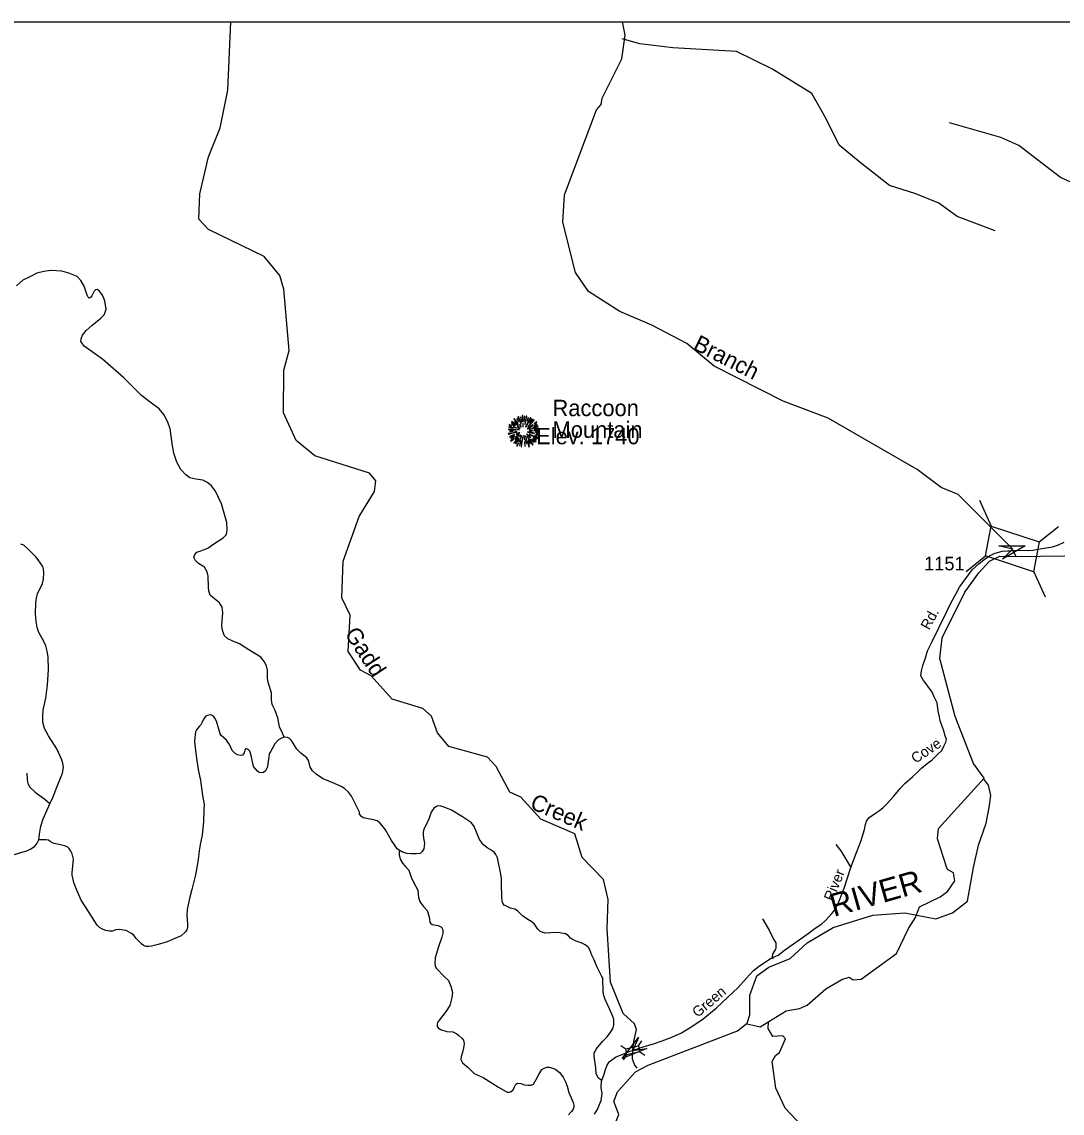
# Model space of a CAD drawing. Extents: x 990631 to 1056237, y 535999 to 585651.
# Drawn here: x 1012421 to 1021960, y 575643 to 585651 of the extents above; entities that cross this region are included whole.
import ezdxf

# ---------------------------------------------------------------- set-up
doc = ezdxf.new("R2010")
doc.units = 0
for name, color, linetype in [('Exist Geographical Mountain Summit CELL', 7, 'Continuous'), ('Exist Geographical Mountain Summit Elevation Number Label', 7, 'Continuous'), ('Exist Geographical Mountain Summit Label', 7, 'Continuous'), ('Exist Hydrographic Creek Single Shore', 7, 'Continuous'), ('Exist Hydrographic Creek Single Shore Label', 7, 'Continuous'), ('Exist Hydrographic River Shore', 7, 'Continuous'), ('Exist Hydrographic River Shore Label', 7, 'Continuous'), ('Exist Road Non-System Type 51', 7, 'Continuous'), ('Exist Road Secondary Structure Standard Bridge Attributed CELL', 7, 'Continuous'), ('Exist Road Secondary Structure Standard Bridge CELL', 7, 'Continuous'), ('Exist Road Secondary Type 51 Attributed', 7, 'Continuous'), ('Exist Road Secondary Type 51 Label', 7, 'Continuous'), ('Exist Road Secondary Type 51 Number Label', 7, 'Continuous'), ('Scratch_Level_3', 7, 'Continuous')]:
    doc.layers.add(name, color=color, linetype=linetype)

msp = doc.modelspace()

# ---------------------------------------------------------------- linework, layer by layer
at = {"layer": 'Exist Geographical Mountain Summit CELL'}
for points in [[(1016911, 581982), (1016951, 581952), (1016953, 581954), (1016915, 581987)], [(1016931, 582007), (1016967, 581970), (1016971, 581972), (1016935, 582012)], [(1016939, 581980), (1016972, 581951), (1016974, 581953), (1016942, 581985)], [(1016959, 582009), (1016975, 581987), (1016976, 581988), (1016963, 582013)], [(1016970, 582030), (1016996, 581964), (1016999, 581965), (1016975, 582033)], [(1017004, 581979), (1017006, 581979), (1016997, 582027), (1016993, 582026)], [(1017008, 582040), (1017013, 581988), (1017016, 581988), (1017014, 582041)], [(1017024, 581986), (1017028, 581986), (1017032, 582033), (1017027, 582033)], [(1017036, 581957), (1017051, 582034), (1017046, 582036), (1017033, 581958)], [(1017040, 581936), (1017043, 581934), (1017091, 582018), (1017086, 582022)], [(1017054, 581993), (1017058, 581992), (1017067, 582018), (1017062, 582020)], [(1017061, 581937), (1017063, 581935), (1017119, 581999), (1017115, 582004)], [(1017098, 582009), (1017077, 581975), (1017080, 581974), (1017103, 582005)], [(1017119, 581965), (1017120, 581963), (1017143, 581979), (1017140, 581982)], [(1016881, 581875), (1016883, 581869), (1016919, 581880), (1016917, 581883)], [(1016883, 581912), (1016955, 581905), (1016955, 581908), (1016883, 581917)], [(1016885, 581933), (1016927, 581924), (1016928, 581927), (1016886, 581938)], [(1016888, 581953), (1016911, 581944), (1016912, 581947), (1016890, 581958)], [(1016895, 581895), (1016924, 581896), (1016924, 581900), (1016894, 581900)], [(1016910, 581964), (1016936, 581947), (1016938, 581950), (1016913, 581968)], [(1016927, 581936), (1016957, 581924), (1016958, 581926), (1016929, 581940)], [(1016927, 581886), (1016928, 581881), (1016961, 581889), (1016961, 581893)], [(1016955, 581872), (1016957, 581867), (1016986, 581882), (1016985, 581885)], [(1016963, 581941), (1016988, 581922), (1016990, 581925), (1016966, 581944)], [(1016963, 581911), (1016980, 581909), (1016981, 581911), (1016964, 581916)], [(1016983, 581954), (1016996, 581938), (1016999, 581940), (1016986, 581957)], [(1017014, 581967), (1017015, 581937), (1017018, 581938), (1017018, 581967)], [(1017058, 581917), (1017059, 581915), (1017108, 581951), (1017105, 581955)], [(1017059, 581888), (1017120, 581876), (1017121, 581880), (1017060, 581891)], [(1017074, 581901), (1017074, 581899), (1017104, 581899), (1017104, 581904)], [(1017075, 581914), (1017076, 581912), (1017154, 581941), (1017152, 581945)], [(1017119, 581942), (1017146, 581957), (1017143, 581962), (1017117, 581945)], [(1017117, 581900), (1017169, 581904), (1017169, 581908), (1017117, 581904)], [(1017120, 581914), (1017157, 581921), (1017156, 581926), (1017119, 581916)], [(1017132, 581888), (1017158, 581886), (1017158, 581891), (1017132, 581892)], [(1016891, 581847), (1016894, 581842), (1016939, 581862), (1016938, 581867)], [(1016902, 581810), (1016905, 581806), (1016934, 581827), (1016931, 581831)], [(1016909, 581831), (1016938, 581848), (1016935, 581851), (1016906, 581836)], [(1016933, 581791), (1016936, 581788), (1016977, 581836), (1016974, 581838)], [(1016949, 581822), (1016968, 581840), (1016964, 581842), (1016944, 581825)], [(1016945, 581840), (1016948, 581837), (1016982, 581865), (1016980, 581868)], [(1016973, 581822), (1016948, 581783), (1016951, 581780), (1016977, 581820)], [(1016958, 581763), (1016963, 581760), (1016974, 581785), (1016971, 581787)], [(1016976, 581800), (1016981, 581799), (1017007, 581857), (1017005, 581858)], [(1016983, 581850), (1016987, 581847), (1016997, 581863), (1016995, 581865)], [(1016988, 581765), (1017000, 581808), (1016996, 581808), (1016984, 581766)], [(1016998, 581755), (1017003, 581754), (1017015, 581843), (1017012, 581844)], [(1017023, 581859), (1017027, 581822), (1017032, 581822), (1017027, 581860)], [(1017030, 581800), (1017033, 581758), (1017037, 581759), (1017034, 581800)], [(1017039, 581850), (1017048, 581820), (1017052, 581822), (1017041, 581851)], [(1017049, 581784), (1017044, 581814), (1017040, 581814), (1017045, 581783)], [(1017048, 581871), (1017086, 581835), (1017089, 581840), (1017050, 581873)], [(1017054, 581848), (1017104, 581773), (1017108, 581776), (1017056, 581849)], [(1017054, 581805), (1017071, 581755), (1017076, 581757), (1017057, 581806)], [(1017064, 581811), (1017080, 581782), (1017084, 581784), (1017068, 581812)], [(1017073, 581868), (1017151, 581830), (1017153, 581835), (1017074, 581871)], [(1017086, 581822), (1017116, 581793), (1017120, 581796), (1017088, 581825)], [(1017103, 581823), (1017133, 581797), (1017137, 581801), (1017105, 581826)], [(1017112, 581834), (1017137, 581821), (1017140, 581824), (1017114, 581838)], [(1017126, 581858), (1017147, 581850), (1017149, 581854), (1017128, 581861)], [(1017136, 581871), (1017164, 581864), (1017165, 581869), (1017137, 581876)]]:
    msp.add_lwpolyline(points, close=True, dxfattribs=at)
at = {"layer": 'Exist Hydrographic Creek Single Shore'}
for points in [[(1018062, 576055), (1018038, 576089), (1018020, 576137), (1018024, 576222), (1018031, 576299), (1018056, 576411), (1018038, 576463), (1017936, 576557), (1017818, 576845), (1017789, 577337), (1017798, 577603), (1017754, 577787), (1017560, 577988), (1017493, 578206), (1017180, 578340), (1016995, 578541), (1016897, 578586), (1016771, 578821), (1016691, 578908), (1016335, 579004), (1016231, 579131), (1016178, 579283), (1016097, 579353), (1015816, 579438), (1015623, 579652), (1015525, 579706), (1015414, 579876), (1015433, 580210), (1015355, 580369), (1015366, 580704), (1015513, 581114), (1015655, 581345), (1015666, 581443), (1015610, 581513), (1015107, 581671), (1014936, 581812), (1014820, 582064), (1014824, 582458), (1014872, 582637), (1014824, 583199), (1014787, 583325), (1014642, 583498), (1014134, 583748), (1014045, 583842), (1014053, 584075), (1014131, 584414), (1014240, 584678), (1014310, 585025), (1014338, 585651)], [(1021538, 580749), (1021499, 580823), (1021007, 581316), (1020851, 581381), (1020631, 581546), (1019813, 582016), (1019401, 582172), (1018770, 582493), (1018518, 582701), (1018199, 582869), (1017903, 582996), (1017617, 583179), (1017498, 583352), (1017380, 583814), (1017396, 584063), (1017689, 584845), (1017733, 584893), (1017743, 584952), (1017922, 585313), (1017954, 585529), (1017930, 585651)], [(1021345, 583733), (1020996, 583867), (1020829, 583988), (1020617, 584075), (1020376, 584150), (1020109, 584362), (1019914, 584521), (1019797, 584762), (1019664, 584995), (1019298, 585220), (1018973, 585378), (1018390, 585412), (1018086, 585449), (1017924, 585495)], [(1022224, 584098), (1021945, 584222), (1021563, 584518), (1021399, 584590), (1020928, 584725)], [(1019069, 576461), (1019152, 576444), (1019191, 576434), (1019430, 576580), (1019550, 576604), (1019623, 576633), (1019792, 576783), (1019941, 576869), (1020007, 576889), (1020044, 576866), (1020117, 576872), (1020441, 577107), (1020550, 577336), (1020614, 577438), (1020653, 577535), (1020842, 577628), (1020909, 577677), (1020975, 577774), (1020965, 577847), (1020909, 577877), (1020899, 577902), (1020816, 578158), (1020825, 578254), (1020972, 578416), (1021244, 578714)], [(1023226, 574096), (1023161, 574140), (1023081, 574234), (1022486, 574403), (1022213, 574731), (1021668, 574889), (1021391, 575065), (1021135, 575166), (1020820, 575218), (1020196, 575241), (1019826, 575419), (1019573, 575526), (1019420, 575689), (1019334, 575871), (1019301, 576117), (1019331, 576173), (1019367, 576200), (1019424, 576326), (1019400, 576353), (1019307, 576346), (1019264, 576419), (1019268, 576481)]]:
    msp.add_lwpolyline(points, dxfattribs=at)
at = {"layer": 'Exist Hydrographic River Shore'}
for points in [[(1021244, 578714), (1021147, 578851), (1020978, 579281), (1020837, 579812), (1020860, 580002), (1021066, 580422), (1021197, 580599), (1021293, 580705), (1021388, 580752), (1021538, 580749)], [(1021538, 580749), (1021984, 580755)], [(1019161, 576902), (1019271, 576982), (1019467, 577062), (1019623, 577204), (1019861, 577347), (1020225, 577459), (1020517, 577479), (1020802, 577426), (1020955, 577479), (1021091, 577586), (1021147, 577897), (1021194, 578100), (1021263, 578303), (1021290, 578446), (1021307, 578556), (1021283, 578652), (1021240, 578712)], [(1019072, 576468), (1019095, 576544), (1019095, 576726), (1019161, 576902)], [(1018164, 576082), (1018982, 576398), (1019072, 576468)], [(1017640, 575384), (1017849, 575518), (1017896, 575631), (1017849, 575751), (1017884, 575838), (1018048, 576021), (1018164, 576082)]]:
    msp.add_lwpolyline(points, dxfattribs=at)
at = {"layer": 'Exist Road Non-System Type 51'}
for points in [[(1014827, 579090), (1014810, 579128), (1014784, 579185), (1014767, 579268), (1014743, 579337), (1014717, 579392), (1014710, 579432), (1014711, 579498), (1014687, 579575), (1014678, 579607), (1014675, 579637), (1014673, 579705), (1014665, 579746), (1014642, 579786), (1014611, 579824), (1014502, 579893), (1014417, 579948), (1014348, 579974), (1014309, 579992), (1014280, 580021), (1014263, 580059), (1014255, 580106), (1014259, 580164), (1014261, 580189), (1014263, 580235), (1014257, 580284), (1014234, 580322), (1014171, 580371), (1014148, 580393), (1014137, 580434), (1014132, 580468), (1014130, 580566), (1014121, 580608), (1014097, 580651), (1014042, 580685), (1014009, 580714), (1013997, 580739), (1014006, 580766), (1014025, 580788), (1014063, 580800), (1014126, 580824), (1014182, 580863), (1014268, 580920), (1014294, 580947), (1014301, 580967), (1014304, 580998), (1014300, 581061), (1014252, 581230), (1014198, 581348), (1014159, 581396), (1014117, 581429), (1014081, 581448), (1014017, 581456), (1013960, 581470), (1013925, 581496), (1013878, 581547), (1013841, 581612), (1013815, 581695), (1013803, 581762), (1013781, 581919), (1013761, 581979), (1013723, 582049), (1013679, 582102), (1013599, 582163), (1013517, 582224), (1013356, 582387), (1013160, 582556), (1012991, 582676), (1012970, 582706), (1012963, 582721), (1012966, 582744), (1012977, 582778), (1013012, 582821), (1013062, 582867), (1013144, 582935), (1013177, 582965), (1013186, 582987), (1013195, 583017), (1013183, 583091), (1013161, 583144), (1013130, 583185), (1013113, 583196), (1013097, 583192), (1013084, 583181), (1013063, 583137), (1013050, 583122), (1013038, 583118), (1013028, 583125), (1013019, 583143), (1012992, 583228), (1012963, 583279), (1012927, 583316), (1012852, 583347), (1012788, 583365), (1012688, 583370), (1012622, 583362), (1012559, 583346), (1012494, 583313), (1012431, 583281), (1012371, 583229)], [(1012679, 578483), (1012701, 578528), (1012742, 578631), (1012795, 578761), (1012803, 578813), (1012796, 578853), (1012785, 578888), (1012742, 578983), (1012666, 579102), (1012630, 579171), (1012614, 579228), (1012615, 579252), (1012614, 579280), (1012618, 579338), (1012642, 579449), (1012656, 579571), (1012664, 579710), (1012662, 579829), (1012654, 579881), (1012640, 579929), (1012617, 579980), (1012578, 580050), (1012563, 580098), (1012551, 580151), (1012545, 580225), (1012549, 580321), (1012554, 580367), (1012566, 580410), (1012585, 580448), (1012609, 580499), (1012620, 580540), (1012624, 580600), (1012621, 580632), (1012612, 580655), (1012572, 580716), (1012549, 580745), (1012481, 580813), (1012438, 580851), (1012412, 580860)], [(1014827, 579090), (1014801, 579083), (1014774, 579068), (1014741, 579029), (1014703, 578964), (1014690, 578938), (1014685, 578908), (1014677, 578849), (1014672, 578819), (1014665, 578801), (1014655, 578783), (1014638, 578768), (1014616, 578765), (1014598, 578767), (1014581, 578778), (1014544, 578821), (1014523, 578924), (1014513, 578962), (1014497, 578979), (1014485, 578985), (1014471, 578984), (1014467, 578972), (1014460, 578948), (1014445, 578926), (1014427, 578923), (1014397, 578930), (1014378, 578941), (1014351, 578970), (1014324, 579024), (1014298, 579063), (1014249, 579105), (1014240, 579123), (1014207, 579237), (1014192, 579265), (1014177, 579284), (1014161, 579292), (1014147, 579295), (1014123, 579291), (1014109, 579284), (1014086, 579255), (1014073, 579229), (1014062, 579205), (1014048, 579188), (1014021, 579159), (1014014, 579141), (1014009, 579113), (1014006, 579087), (1014003, 579047), (1014019, 578919), (1014039, 578796), (1014059, 578695), (1014079, 578556), (1014092, 578474), (1014091, 578428), (1014087, 578318), (1014075, 578192), (1014058, 578123), (1014049, 578069), (1014034, 577947), (1014012, 577830), (1013980, 577695), (1013959, 577612), (1013948, 577568), (1013938, 577512), (1013934, 577456), (1013939, 577380), (1013940, 577346), (1013933, 577324), (1013923, 577307), (1013882, 577270), (1013825, 577244), (1013752, 577214), (1013671, 577189), (1013610, 577173), (1013584, 577170), (1013562, 577171), (1013536, 577179), (1013519, 577196), (1013469, 577244), (1013444, 577279), (1013420, 577293), (1013379, 577319), (1013353, 577322), (1013317, 577327), (1013283, 577324), (1013249, 577313), (1013225, 577312), (1013187, 577317), (1013155, 577332), (1013134, 577347), (1013112, 577366), (1013033, 577491), (1012966, 577597), (1012916, 577709), (1012899, 577757), (1012882, 577824), (1012882, 577848), (1012894, 577971), (1012882, 578020), (1012869, 578046)], [(1015881, 578054), (1015862, 578067), (1015837, 578103), (1015812, 578142), (1015755, 578240), (1015723, 578285), (1015702, 578306), (1015678, 578323), (1015648, 578334), (1015595, 578342), (1015551, 578351), (1015535, 578362), (1015518, 578386), (1015516, 578402), (1015479, 578478), (1015443, 578549), (1015417, 578586), (1015378, 578619), (1015350, 578638), (1015289, 578666), (1015183, 578708), (1015122, 578748), (1015087, 578783), (1015064, 578816), (1015052, 578870), (1015035, 578901), (1014978, 578945), (1014942, 578980), (1014909, 579035), (1014892, 579062), (1014875, 579080), (1014857, 579087), (1014827, 579090)], [(1012467, 578762), (1012469, 578706), (1012472, 578676), (1012479, 578662), (1012492, 578635), (1012543, 578586), (1012631, 578521), (1012679, 578483)], [(1012576, 578150), (1012584, 578200), (1012596, 578274), (1012617, 578341), (1012643, 578402), (1012675, 578473), (1012679, 578483)], [(1017738, 575942), (1017717, 575957), (1017709, 575965), (1017694, 575990), (1017688, 576004), (1017684, 576060), (1017669, 576165), (1017670, 576195), (1017677, 576209), (1017688, 576230), (1017746, 576299), (1017788, 576343), (1017821, 576388), (1017840, 576419), (1017849, 576449), (1017850, 576477), (1017849, 576501), (1017840, 576528), (1017810, 576599), (1017769, 576686), (1017756, 576722), (1017751, 576755), (1017749, 576881), (1017740, 576897), (1017693, 576989), (1017669, 577048), (1017646, 577092), (1017630, 577141), (1017617, 577161), (1017585, 577186), (1017550, 577204), (1017504, 577219), (1017469, 577236), (1017451, 577249), (1017430, 577272), (1017407, 577286), (1017369, 577294), (1017343, 577301), (1017271, 577297), (1017219, 577295), (1017193, 577302), (1017173, 577310), (1017152, 577331), (1017121, 577376), (1017098, 577399), (1017061, 577418), (1017012, 577454), (1016965, 577497), (1016940, 577514), (1016902, 577523), (1016859, 577543), (1016845, 577551), (1016830, 577568), (1016824, 577586), (1016821, 577624), (1016819, 577742), (1016819, 577798), (1016811, 577851), (1016781, 577984), (1016768, 578014), (1016753, 578035), (1016714, 578060), (1016688, 578075), (1016653, 578104), (1016617, 578153), (1016595, 578204), (1016569, 578271), (1016544, 578306), (1016462, 578359), (1016362, 578422), (1016293, 578450), (1016263, 578459), (1016245, 578460), (1016229, 578457), (1016200, 578441), (1016175, 578404), (1016155, 578347), (1016131, 578294), (1016110, 578252), (1016103, 578236), (1016101, 578221), (1016102, 578197), (1016103, 578164), (1016112, 578118), (1016111, 578090), (1016108, 578066), (1016093, 578041), (1016072, 578025), (1016036, 578021), (1015992, 578020), (1015952, 578025), (1015905, 578039), (1015891, 578048), (1015881, 578054)], [(1012152, 577806), (1012168, 577864), (1012186, 577923), (1012197, 577949), (1012208, 577964), (1012226, 577976), (1012299, 578003), (1012364, 578017), (1012434, 578039), (1012467, 578050), (1012503, 578067), (1012538, 578087), (1012557, 578113), (1012576, 578150)], [(1012869, 578046), (1012856, 578069), (1012844, 578081), (1012816, 578096), (1012745, 578109), (1012709, 578118), (1012682, 578133), (1012666, 578147), (1012642, 578150), (1012576, 578150)], [(1019886, 578108), (1019932, 578049), (1019966, 577988), (1020023, 577896)], [(1015881, 578054), (1015881, 578036), (1015882, 578012), (1015891, 577973), (1015911, 577935), (1015932, 577910), (1015969, 577871), (1015991, 577806), (1016010, 577767), (1016053, 577688), (1016059, 577620), (1016070, 577583), (1016081, 577567), (1016102, 577540), (1016139, 577501), (1016157, 577442), (1016161, 577396), (1016167, 577384), (1016183, 577373), (1016238, 577365), (1016270, 577348), (1016281, 577324), (1016280, 577294), (1016273, 577258), (1016240, 577167), (1016210, 577066), (1016209, 577020), (1016212, 576992), (1016223, 576970), (1016293, 576897), (1016332, 576860), (1016356, 576807), (1016370, 576749), (1016363, 576705), (1016344, 576631), (1016312, 576577), (1016252, 576498), (1016233, 576473), (1016228, 576459), (1016228, 576439), (1016239, 576425), (1016259, 576410), (1016318, 576392), (1016374, 576388), (1016409, 576369), (1016429, 576356), (1016456, 576332), (1016471, 576311), (1016476, 576283), (1016474, 576257), (1016460, 576199), (1016450, 576164), (1016447, 576134), (1016461, 576105), (1016513, 576061), (1016569, 576008), (1016650, 575971), (1016793, 575880), (1016872, 575837), (1016894, 575837), (1016908, 575842), (1016925, 575858), (1016938, 575885), (1016952, 575909), (1016967, 575918), (1016999, 575915), (1017026, 575904), (1017062, 575899), (1017092, 575900), (1017111, 575909), (1017138, 575952), (1017160, 575998), (1017189, 576043), (1017209, 576056), (1017238, 576065), (1017260, 576064), (1017288, 576057), (1017313, 576045), (1017350, 576015), (1017383, 575972), (1017407, 575929), (1017420, 575889), (1017438, 575832), (1017449, 575804), (1017475, 575741), (1017482, 575715), (1017482, 575701), (1017475, 575681), (1017462, 575657), (1017433, 575628)], [(1019212, 577424), (1019273, 577320), (1019314, 577239), (1019333, 577206), (1019334, 577182), (1019336, 577158), (1019331, 577146), (1019308, 577107), (1019304, 577099), (1019301, 577077), (1019306, 577059)]]:
    msp.add_lwpolyline(points, dxfattribs=at)
at = {"layer": 'Exist Road Secondary Structure Standard Bridge Attributed CELL'}
for points in [[(1021378, 580845), (1021622, 580846), (1021412, 580723), (1021504, 580814)], [(1018152, 576237), (1017927, 576144), (1018075, 576337), (1018024, 576218)]]:
    msp.add_lwpolyline(points, close=True, dxfattribs=at)
at = {"layer": 'Exist Road Secondary Structure Standard Bridge CELL'}
for p, q in [((1021201, 581264), (1021308, 581027)), ((1021748, 580881), (1021925, 581024)), ((1021080, 580611), (1021257, 580753)), ((1021698, 580613), (1021805, 580377)), ((1018076, 576259), (1018106, 576305)), ((1017912, 576264), (1017958, 576234)), ((1017939, 576132), (1017969, 576179)), ((1018087, 576205), (1018134, 576174))]:
    msp.add_line(p, q, dxfattribs=at)
for points in [[(1021308, 581027), (1021748, 580882), (1021697, 580608), (1021257, 580753)], [(1017958, 576234), (1018076, 576259), (1018088, 576204), (1017969, 576179)]]:
    msp.add_lwpolyline(points, close=True, dxfattribs=at)
at = {"layer": 'Exist Road Secondary Type 51 Attributed'}
for points in [[(1021462, 580799), (1021483, 580801), (1021567, 580806), (1021647, 580803), (1021691, 580806), (1021723, 580813), (1021777, 580822), (1021872, 580838), (1021925, 580856), (1021977, 580880)], [(1018000, 576210), (1018040, 576224), (1018127, 576253), (1018203, 576277), (1018292, 576307), (1018382, 576340), (1018470, 576381), (1018563, 576438), (1018669, 576509), (1018786, 576606), (1018896, 576710), (1018987, 576793), (1019062, 576879), (1019129, 576950), (1019185, 576995), (1019291, 577063), (1019355, 577091), (1019415, 577137), (1019630, 577292), (1019694, 577338), (1019757, 577380), (1019794, 577413), (1019847, 577475), (1019878, 577512), (1019903, 577559), (1019919, 577597), (1019962, 577706), (1020023, 577896), (1020073, 578033), (1020118, 578143), (1020147, 578245), (1020158, 578290), (1020167, 578320), (1020189, 578353), (1020239, 578387), (1020286, 578419), (1020318, 578445), (1020354, 578483), (1020415, 578550), (1020476, 578621), (1020517, 578666), (1020588, 578726), (1020638, 578774), (1020671, 578806), (1020721, 578850), (1020769, 578883), (1020821, 578936), (1020856, 578968), (1020876, 579008), (1020893, 579045), (1020898, 579071), (1020887, 579104), (1020871, 579158), (1020855, 579207), (1020842, 579240), (1020834, 579277), (1020822, 579330), (1020815, 579406), (1020786, 579462), (1020767, 579504), (1020714, 579579), (1020687, 579611), (1020663, 579654), (1020669, 579698), (1020683, 579747), (1020706, 579819), (1020724, 579882), (1020766, 579962), (1020830, 580094), (1020898, 580237), (1020940, 580320), (1020987, 580409), (1021019, 580468), (1021059, 580523), (1021101, 580579), (1021136, 580626), (1021196, 580680), (1021246, 580721), (1021293, 580755), (1021336, 580776), (1021409, 580796), (1021462, 580799)], [(1017671, 575634), (1017703, 575683), (1017716, 575717), (1017732, 575759), (1017742, 575822), (1017732, 575875), (1017736, 575938), (1017738, 575942), (1017760, 576000), (1017769, 576035), (1017786, 576076), (1017807, 576114), (1017863, 576156), (1018000, 576210)]]:
    msp.add_lwpolyline(points, dxfattribs=at)
at = {"layer": 'Scratch_Level_3'}
msp.add_lwpolyline([(1056237, 535999), (990631, 535999), (990631, 585651), (1056237, 585651)], close=True, dxfattribs=at)

# ---------------------------------------------------------------- texts
at = {"layer": 'Exist Geographical Mountain Summit Elevation Number Label'}
msp.add_text('Elev. 1740', height=150, dxfattribs=at).set_placement((1017137, 581777))
at = {"layer": 'Exist Geographical Mountain Summit Label'}
for s, p in [('Raccoon', (1017287, 582035)), ('Mountain', (1017287, 581836))]:
    msp.add_text(s, height=150, dxfattribs=at).set_placement(p)
at = {"layer": 'Exist Hydrographic Creek Single Shore Label'}
for s, rotation, p in [('Branch', 333.0381, (1018566, 582652)), ('Gadd', 303.2078, (1015375, 580039)), ('Creek', 336.7345, (1017071, 578441))]:
    msp.add_text(s, height=150, rotation=rotation, dxfattribs=at).set_placement(p)
at = {"layer": 'Exist Hydrographic River Shore Label'}
msp.add_text('RIVER', height=210, rotation=15.8504, dxfattribs=at).set_placement((1019865, 577442))
at = {"layer": 'Exist Road Secondary Type 51 Label'}
for s, rotation, p in [('Rd.', 61.5462, (1020740, 580068)), ('Cove', 33.7776, (1020615, 578846)), ('River', 68.1541, (1019859, 577580)), ('Green', 40.112, (1018617, 576515))]:
    msp.add_text(s, height=95, rotation=rotation, dxfattribs=at).set_placement(p)
at = {"layer": 'Exist Road Secondary Type 51 Number Label'}
msp.add_text('1151', height=125, dxfattribs=at).set_placement((1020694, 580621))

doc.saveas('drawing.dxf')
